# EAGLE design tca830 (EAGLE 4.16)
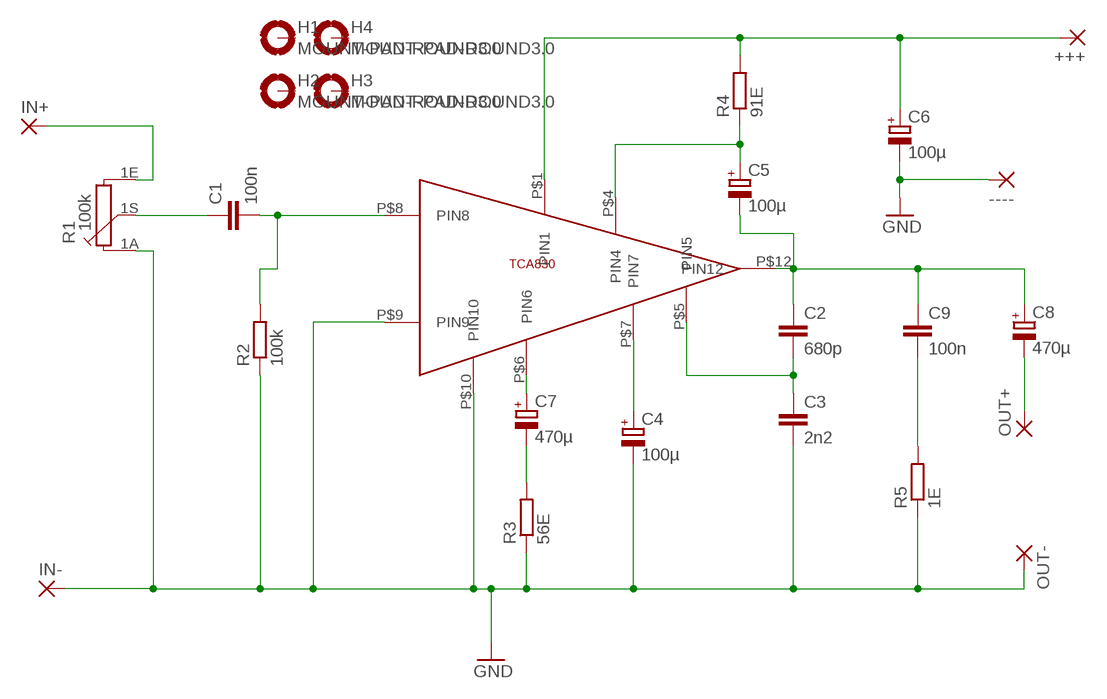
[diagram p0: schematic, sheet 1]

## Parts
+++  2,54/0,8  [2,54/0,8]
----  2,54/0,8  [2,54/0,8]
C1  100n  C-EU050-025X075  [C050-025X075]
C2  680p  C-EU050-025X075  [C050-025X075]
C3  2n2  C-EU050-025X075  [C050-025X075]
C4  100µ  CPOL-EUE2.5-6  [E2,5-6]
C5  100µ  CPOL-EUE2.5-6  [E2,5-6]
C6  100µ  CPOL-EUE2.5-6  [E2,5-6]
C7  470µ  CPOL-EUE2.5-7  [E2,5-7]
C8  470µ  CPOL-EUE2.5-7  [E2,5-7]
C9  100n  C-EU050-025X075  [C050-025X075]
H1  MOUNT-PAD-ROUND3.0  [3,0-PAD]
H2  MOUNT-PAD-ROUND3.0  [3,0-PAD]
H3  MOUNT-PAD-ROUND3.0  [3,0-PAD]
H4  MOUNT-PAD-ROUND3.0  [3,0-PAD]
IN+  2,54/0,8  [2,54/0,8]
IN-  2,54/0,8  [2,54/0,8]
OUT+  2,54/0,8  [2,54/0,8]
OUT-  2,54/0,8  [2,54/0,8]
R1  100k  PC16S  [PC16S]
R2  100k  R-EU_0207/7  [0207/7]
R3  56E  R-EU_0207/7  [0207/7]
R4  91E  R-EU_0207/7  [0207/7]
R5  1E  R-EU_0207/7  [0207/7]
U$1  TCA830  [TCA830]

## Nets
GND: ----.1(P) C3.2 C4.- C6.- IN-.1(P) OUT-.1(P) R1.1A R2.1 R3.1 R5.1 U$1.P$9(PIN9) U$1.P$10(PIN10)
N$2: C1.1 R1.1S
N$3: C1.2 R2.2 U$1.P$8(PIN8)
N$4: IN+.1(P) R1.1E
N$5: C7.- R3.2
N$6: C7.+ U$1.P$6(PIN6)
N$7: C4.+ U$1.P$7(PIN7)
N$8: C2.2 C3.1 U$1.P$5(PIN5)
N$9: C9.2 R5.2
N$11: C2.1 C5.- C8.+ C9.1 U$1.P$12(PIN12)
N$12: C5.+ R4.1 U$1.P$4(PIN4)
N$14: C8.- OUT+.1(P)
N$15: +++.1(P) C6.+ R4.2 U$1.P$1(PIN1)
Unconnected: H1.B3,0(MOUNT) H2.B3,0(MOUNT) H3.B3,0(MOUNT) H4.B3,0(MOUNT)

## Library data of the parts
+++ ---- IN+ IN- OUT+ OUT- = wirepad:2,54/0,8: THROUGH-HOLE PAD
C1-C3 C9 = rcl:C-EU: CAPACITOR, European symbol
C4-C8 = rcl:CPOL-EU: POLARIZED CAPACITOR, European symbol
H1-H4 = holes:MOUNT-PAD-ROUND: MOUNTING PAD, round
R1 = piher:PC16S: POTENTIOMETER single carbon potentiometer, 16 mm, S3ROH
R2-R5 = rcl:R-EU_: RESISTOR, European symbol
U$1 = tca830:TCA830

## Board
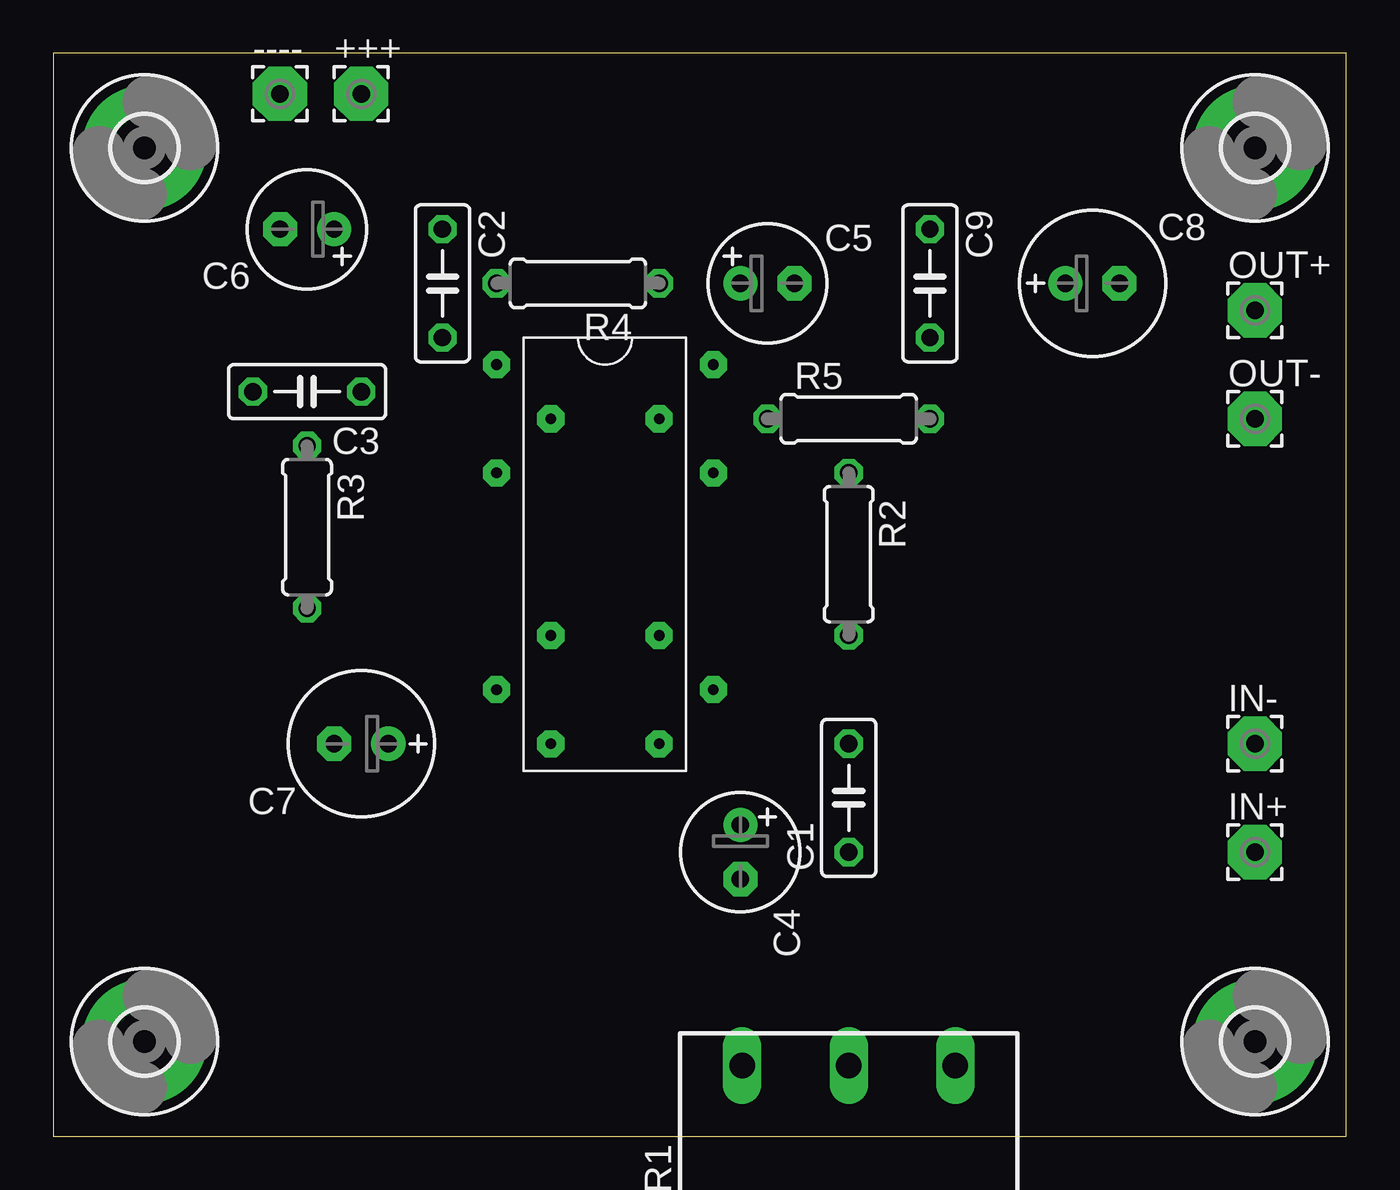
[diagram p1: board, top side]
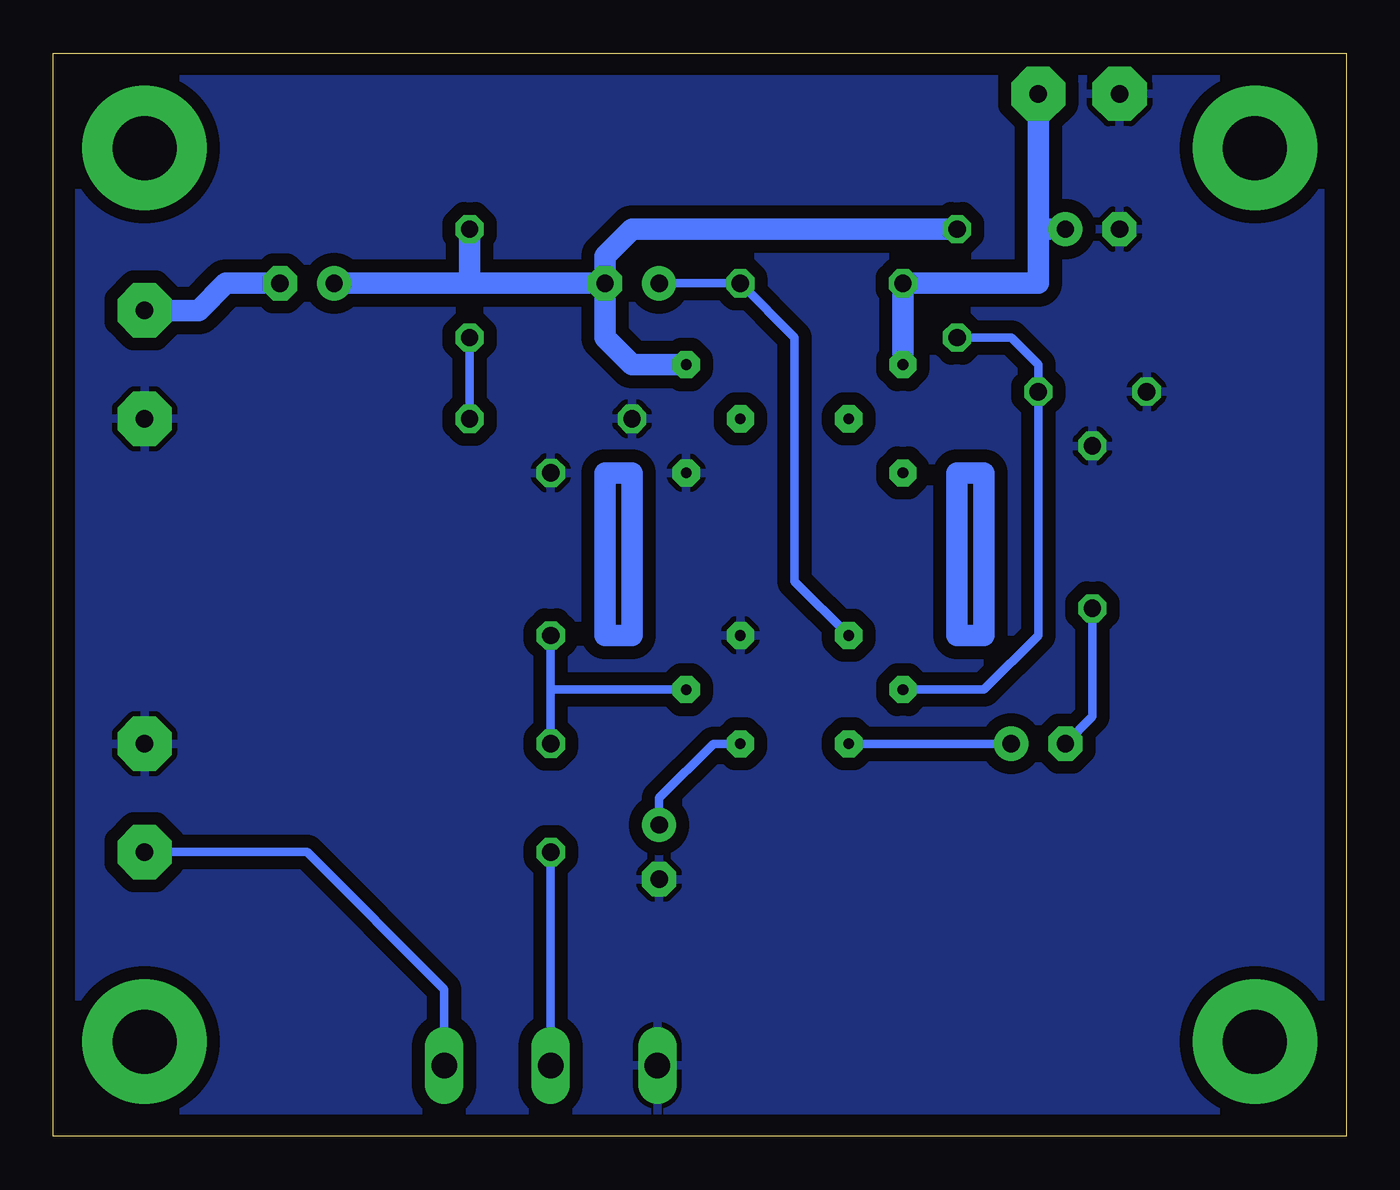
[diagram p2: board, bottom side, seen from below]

Size 60.63 x 50.79 mm. Coordinates in mm from the lower left corner, seen from the top.
Outline: 0,0 60.63,0 60.63,50.79 0,50.79 0,0
Copper layers (1*16): Top 0.035mm / dielectric 1.5mm / Bottom 0.035mm
Design rules "default": minimum track width 10mil, minimum drill 24mil, track to track 8mil, track to pad 8mil, pad to pad 8mil, via to via 8mil, smd to smd 8mil, copper to edge 40mil, drill to drill 8mil, minimum pad ring 10mil, minimum via ring 8mil, stop-mask expansion 4mil, vias tented up to drill 0mil, thermal gap 10mil

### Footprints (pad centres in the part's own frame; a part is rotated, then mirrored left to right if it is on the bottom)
2,54/0,8 = drill 0.813 pad 2.54 octagon: 1 0,0
C050-025X075 = drill 0.813 octagon: 1 -2.54,0; 2 2.54,0
E2,5-6 = drill 0.813 pad 1.6 round: + -1.27,0 | drill 0.813 pad 1.6 octagon: - 1.27,0
E2,5-7 = drill 0.813 pad 1.6 round: + -1.27,0 | drill 0.813 pad 1.6 octagon: - 1.27,0
3,0-PAD = drill 3 pad 5.842 round: B3,0 0,0
PC16S = drill 1.2 long: 1A -5,6.5; 1E 5,6.5; 1S 0,6.5
0207/7 = drill 0.813 octagon: 1 -3.81,0; 2 3.81,0
TCA830 = drill 0.5 pad 1.27 octagon: P$1 10.16,17.78; P$2 12.7,15.24; P$3 10.16,12.7; P$4 12.7,5.08; P$5 10.16,2.54; P$6 12.7,0; P$7 17.78,0; P$8 20.32,2.54; P$9 17.78,5.08; P$10 20.32,12.7; P$11 17.78,15.24; P$12 20.32,17.78

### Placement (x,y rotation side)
+++  14.44,48.89 0 top
----  10.63,48.89 0 top
C1  37.3,15.87 90 top
C2  18.25,40 270 top
C3  11.9,34.92 180 top
C4  32.22,13.33 270 top
C5  33.49,40 0 top
C6  11.9,42.54 180 top
C7  14.44,18.41 180 top
C8  48.73,40 0 top
C9  41.11,40 270 top
H1  4.28,4.44 0 top
H2  56.35,46.35 0 top
H3  4.28,46.35 0 top
H4  56.35,4.44 0 top
IN+  56.35,13.33 0 top
IN-  56.35,18.41 0 top
OUT+  56.35,38.73 0 top
OUT-  56.35,33.65 0 top
R1  37.3,-3.18 0 top
R2  37.3,27.3 270 top
R3  11.9,28.57 270 top
R4  24.6,40 180 top
R5  37.3,33.65 0 top
U$1  10.63,18.41 0 top

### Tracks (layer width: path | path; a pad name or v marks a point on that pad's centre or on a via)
GND
  pour Bottom (isolate 0.61): -0.8,51.43 61.43,51.43 61.43,-0.64 -0.8,-0.64
N$2
  Bottom 0.406: 37.3,3.17 R1.1S C1.1
N$3
  Bottom 0.406: U$1.P$8 37.3,20.95 | 37.3,20.95 R2.2 | 37.3,20.95 C1.2
N$4
  Bottom 0.406: R1.1E 42.3,6.9 48.73,13.33 IN+.1
N$5
  Bottom 0.406: C7.- 11.9,19.68 R3.2
N$6
  Bottom 0.406: C7.+ U$1.P$6
N$7
  Bottom 0.406: U$1.P$7 29.68,18.41 32.22,15.87 C4.+
N$8
  Bottom 0.406: U$1.P$5 16.98,20.95 14.44,23.49 C3.1 14.44,36.19 15.71,37.46 C2.2
N$9
  Bottom 0.406: R5.2 C9.2
N$11
  Bottom 1.016: C5.- 41.11,40 | 41.11,40 C8.+ | 41.11,40 C9.1 | U$1.P$12 33.49,36.19 34.76,37.46 C5.- | C2.1 33.49,42.54 34.76,41.27 C5.-
N$12
  Bottom 0.406: U$1.P$4 25.87,26.03 25.87,37.46 R4.1 C5.+
N$14
  Bottom 1.016: C8.- 52.54,40 53.81,38.73 OUT+.1
N$15
  Bottom 1.016: 14.44,42.54 +++.1 | 14.44,42.54 C6.+ | 14.44,42.54 14.44,40 R4.2 U$1.P$1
